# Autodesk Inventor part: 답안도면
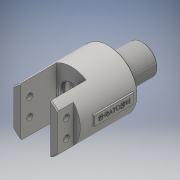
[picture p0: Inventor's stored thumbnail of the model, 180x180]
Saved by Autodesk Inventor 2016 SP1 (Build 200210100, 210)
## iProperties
Created: 2019-02
Part Number: 답안도면
Material: 일반
Document SubType Name: Modeling
Designer: basic
Density: 1 g/cm^3
Appearance: 기본값
Author: basic
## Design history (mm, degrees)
sketch "스케치1"
  geometry: L1 (-54, 0)-(54, 0); L2 (-54, 0)-(-54, 29); L3 (20, 29)-(20, 13); L4 (20, 13)-(25, 13); L5 (25, 13)-(25, 15); L6 (25, 15)-(54, 15); L7 (54, 15)-(54, 0); L8 (-54, 29)-(20, 29); 2 further points
  constraints: 16 end point, 5 perpendicular, 1 coincident, 1 horizontal, 1 midpoint, 1 vertical
  dimensions: "d0" = 108 distance of L1.start L1.end; "d2" = 74 distance between parallel lines of L2 L3; "d3" = 26 diameter of L4 L1; "d4" = 58 diameter of L8 L1; "d5" = 30 diameter of L6 L1; "d6" = 5 distance of L3.end L4.end
revolve "회전1" sketch "스케치1" stored, may be unused: angle "d7" = 90 deg
sketch "스케치2"
  geometry: L1 (29, -54)-(-29, -54) reference; L2 (-15, -54)-(-15, -18); L3 (-15, -18)-(15, -18); L4 (15, -18)-(15, -54); L5 (-15, -54)-(15, -54); 2 further points
  constraints: 8 end point, 2 perpendicular, 2 point on line, 1 collinear, 1 midpoint, 1 vertical, 1 vertical alignment
  dimensions: "d8" = 30 distance of L2.end L3.end; "d9" = 36 distance of L2.start L2.end
extrude "돌출1" cut sketch "스케치2" stored distance "d10" = 10; taper "d11" = 0 deg
sketch "스케치3"
  geometry: L1 (-18, -24.819)-(-18, 24.819) reference; L2 (-18, 14)-(-15.35, 14); L3 (-15.35, 14)-(-15.35, 17); L4 (-15.35, 17)-(-10.65, 17); L5 (-10.65, 17)-(-10.65, 14); L6 (-18, 0)-(54, 0); L7 (54, -15)-(54, 15) reference; L8 (-10.65, 14)-(-6.35, 14); L9 (-6.35, 14)-(-6.35, 17); L10 (-6.35, 17)-(-1.65, 17); L11 (-1.65, 17)-(-1.65, 14); L12 (-1.65, 14)-(2, 14); L13 (2, 14)-(2, 16); L14 (2, 16)-(9, 16); L15 (9, 16)-(9, 0); L16 (-18, 14)-(-18, 0); 1 further point
  constraints: 28 end point, 10 perpendicular, 5 point on line, 2 horizontal, 2 midpoint, 1 collinear
  dimensions: "d12" = 4.7 distance of L3.end L4.end; "d13" = 7 distance of L13.end L14.end; "d14" = 32 diameter of L14 L6; "d16" = 28 diameter of L2 L6; "d17" = 34 diameter of L4 L6; "d18" = 34 diameter of L10 L6; "d20" = 4.3 distance between parallel lines of L9 L5; "d21" = 2.65 distance between parallel lines of L1 L3; "d22" = 20 distance between parallel lines of L13 L1
sketch "스케치4"
  geometry: L1 (29, -54)-(15, -54) reference; L2 (22, -54)-(22, -38); L3 (22, -38)-(29, -38); L4 (29, -54)-(29, 20) reference; L5 (22, -54)-(29, -54); 1 further point
  constraints: 6 end point, 2 perpendicular, 1 collinear, 1 midpoint, 1 point on line
  dimensions: "d28" = 16 distance of L2.start L2.end; "d29" = 22 distance from line of point (0, 0) L2
extrude "돌출2" cut sketch "스케치4" stored distance "d30" = 10; taper "d31" = 0 deg
sketch "스케치5"
  geometry: L1 (-43.714, 0)-(5.925, 0) reference; 2 further points
  dimensions: "d32" = 9 distance from line of L1 point (-27.894, 9); "d33" = 9 horizontal distance of point (-27.894, 9) point (-18.894, 54)
hole "구멍1" sketch "스케치5" at (-27.894, 9) diameter "d34" = 6; stored, may be unused: countersink angle "d38" = 90 deg, drill point angle "d40" = 0 deg; dims "d35" = 6, "d36" = 4, "d37" = 2, "d39" = 8
feature "스레드1" dims "d41" = 10, "d42" = 0
node "작업 평면1"
sketch "스케치6"
  geometry: L1 (-25, 5)-(15, 5); L2 (15, 5)-(15, -5); L3 (15, -5)-(-25, -5); L4 (-25, -5)-(-25, 5); L5 (-25, 5)-(15, -5); L6 (15, 5)-(-25, -5); L7 (20, -29)-(20, 29) reference; 3 further points
  constraints: 12 end point, 3 midpoint, 2 parallel, 1 horizontal, 1 horizontal alignment, 1 perpendicular
  dimensions: "d53" = 40 distance of L1.start L1.end; "d54" = 10 distance of L1.end L2.end; "d55" = 5 distance between parallel lines of L7 L2
extrude "돌출3" join sketch "스케치6" stored distance "d56" = 10; taper "d57" = 0 deg
sketch "스케치7"
  geometry: L1 (5, -25)-(-5, -25) reference; L2 (5, 15)-(5, -25) reference; 2 further points
  constraints: 1 other
  dimensions: "d58" = 20 distance from line of L1 point (0, -5); "d59" = 5 distance from line of L2 point (0, -5)
feature "엠보싱1" sketch "스케치7" dims "d60" = 0.5, "d61" = 0
chamfer "모따기1" distance "d62" = 1; stored, may be unused: second distance "d63" = 2, angle "d64" = 45 deg
revolve "회전3" stored, may be unused: angle "d78" = 90 deg
hole "구멍3" diameter "d81" = 8; stored, may be unused: countersink angle "d85" = 90 deg, drill point angle "d87" = 0 deg; dims "d79" = 10, "d80" = 10, "d82" = 28, "d83" = 4, "d84" = 2, "d86" = 18
hole "구멍4" diameter "d90" = 12.376; stored, may be unused: countersink angle "d94" = 90 deg, drill point angle "d96" = 118 deg; dims "d88" = 10, "d89" = 10, "d91" = 18, "d92" = 4, "d93" = 2, "d95" = 22
fillet "모깎기2" dims "d97" = 0.8
chamfer "모따기4" distance "d98" = 1; stored, may be unused: second distance "d99" = 2, angle "d100" = 45 deg
node "솔리드1"
mirror "대칭1"
mirror "대칭2"
